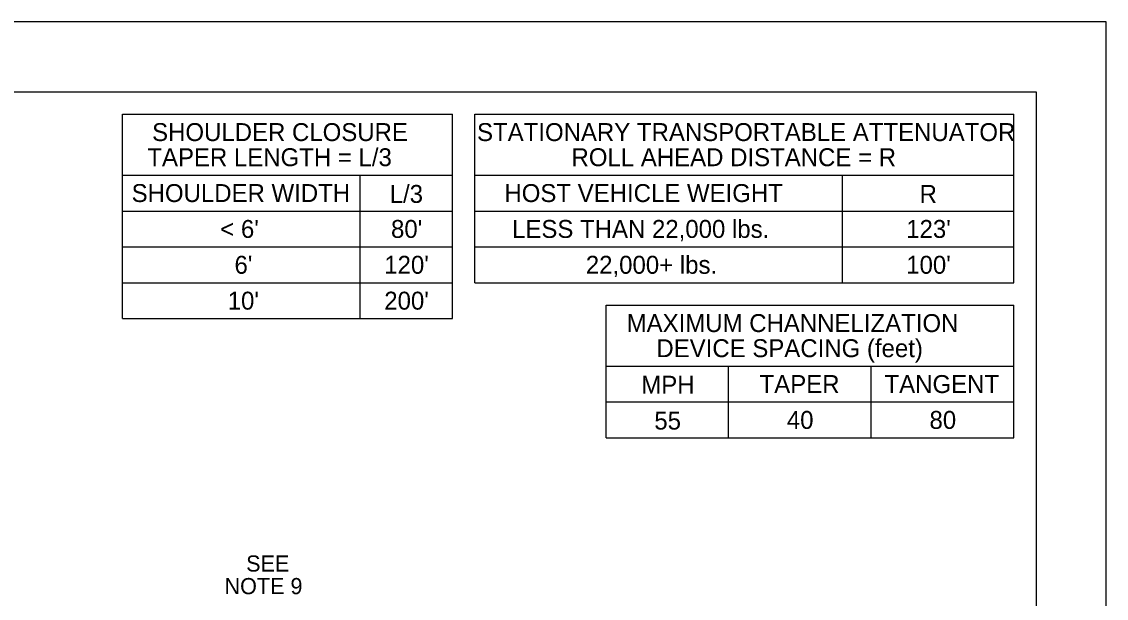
# Model space of a CAD drawing. Extents: x 99999 to 100116, y 99995 to 100013.
# Drawn here: x 100031.224 to 100036.062, y 100008.115 to 100010.687 of the extents above; entities that cross this region are included whole.
import ezdxf

# ---------------------------------------------------------------- set-up
doc = ezdxf.new("R2010")
doc.units = 0
for name, color, linetype in [('SH_GI_PlotLimits', 7, 'Continuous'), ('SH_GI_SheetBorder', 7, 'Continuous'), ('SH_TI_Tables', 7, 'Continuous'), ('TR_SN_ConstructionSigns', 7, 'Continuous')]:
    doc.layers.add(name, color=color, linetype=linetype)

msp = doc.modelspace()

# ---------------------------------------------------------------- linework, layer by layer
at = {"layer": 'SH_GI_PlotLimits'}
msp.add_lwpolyline([(100019.0625, 99999.6875), (100036.0625, 99999.6875), (100036.0625, 100010.6875), (100019.0625, 100010.6875)], close=True, dxfattribs=at)
at = {"layer": 'SH_GI_SheetBorder'}
for p, q in [((100020, 100010.375), (100035.75, 100010.375)), ((100035.75, 100010.375), (100035.75, 100000))]:
    msp.add_line(p, q, dxfattribs=at)
at = {"layer": 'SH_TI_Tables'}
for p, q in [((100031.6742, 100010.275), (100033.1454, 100010.275)), ((100031.6742, 100009.363), (100031.6742, 100010.275)), ((100033.1454, 100009.363), (100033.1454, 100010.275)), ((100033.2454, 100010.275), (100035.65, 100010.275)), ((100033.2454, 100009.523), (100033.2454, 100010.275)), ((100035.65, 100009.523), (100035.65, 100010.275)), ((100031.6742, 100010.003), (100033.1454, 100010.003)), ((100032.7319, 100010.003), (100032.7319, 100009.363)), ((100033.2454, 100010.003), (100034.8844, 100010.003)), ((100034.8844, 100010.003), (100034.8844, 100009.843)), ((100034.8844, 100010.003), (100035.65, 100010.003)), ((100031.6742, 100009.843), (100032.7319, 100009.843)), ((100032.7319, 100009.843), (100033.1454, 100009.843)), ((100033.2454, 100009.843), (100034.8844, 100009.843)), ((100034.8844, 100009.843), (100035.65, 100009.843)), ((100034.8844, 100009.843), (100034.8844, 100009.683)), ((100031.6742, 100009.683), (100032.7319, 100009.683)), ((100032.7319, 100009.683), (100033.1454, 100009.683)), ((100033.2454, 100009.683), (100034.8844, 100009.683)), ((100034.8844, 100009.683), (100035.65, 100009.683)), ((100034.8844, 100009.683), (100034.8844, 100009.523)), ((100031.6742, 100009.523), (100032.7319, 100009.523)), ((100032.7319, 100009.523), (100033.1454, 100009.523)), ((100033.2454, 100009.523), (100035.65, 100009.523)), ((100033.8318, 100009.423), (100035.65, 100009.423)), ((100033.8318, 100008.831), (100033.8318, 100009.423)), ((100035.65, 100008.831), (100035.65, 100009.423)), ((100031.6742, 100009.363), (100032.7319, 100009.363)), ((100032.7319, 100009.363), (100033.1454, 100009.363)), ((100033.8318, 100009.151), (100035.65, 100009.151)), ((100034.3773, 100008.831), (100034.3773, 100009.151)), ((100035.0136, 100008.831), (100035.0136, 100009.151)), ((100033.8318, 100008.991), (100034.3773, 100008.991)), ((100034.3773, 100008.991), (100035.0136, 100008.991)), ((100035.0136, 100008.991), (100035.65, 100008.991)), ((100033.8318, 100008.831), (100035.65, 100008.831))]:
    msp.add_line(p, q, dxfattribs=at)

# ---------------------------------------------------------------- texts
for s, p in [('SHOULDER CLOSURE', (100031.8055, 100010.155)), ('STATIONARY TRANSPORTABLE ATTENUATOR ', (100033.2552, 100010.155)), ('TAPER LENGTH = L/3', (100031.7842, 100010.043)), ('ROLL AHEAD DISTANCE = R', (100033.6767, 100010.043)), ('SHOULDER WIDTH', (100031.7142, 100009.883)), ('L/3', (100032.8654, 100009.8792)), ('HOST VEHICLE WEIGHT', (100033.3773, 100009.883)), ('R', (100035.2296, 100009.8792)), ("< 6'", (100032.1096, 100009.723)), ("80'", (100032.8714, 100009.723)), ('LESS THAN 22,000 lbs.', (100033.4114, 100009.723)), ("123'", (100035.1698, 100009.723)), ("6'", (100032.1731, 100009.563)), ("120'", (100032.8412, 100009.563)), ('22,000+ lbs.', (100033.7405, 100009.563)), ("100'", (100035.1698, 100009.563)), ("10'", (100032.1428, 100009.403)), ("200'", (100032.8412, 100009.403)), ('MAXIMUM CHANNELIZATION', (100033.9227, 100009.303)), ('DEVICE SPACING (feet)', (100034.0553, 100009.191)), ('MPH', (100033.9878, 100009.0279)), ('TAPER', (100034.5157, 100009.031)), ('TANGENT', (100035.0731, 100009.031)), ('40', (100034.6373, 100008.871)), ('80', (100035.2737, 100008.871))]:
    msp.add_text(s, height=0.08, rotation=360, dxfattribs=at).set_placement(p)
msp.add_text('55', height=0.08, dxfattribs=at).set_placement((100034.0461, 100008.8679))
at = {"layer": 'TR_SN_ConstructionSigns'}
for s, p in [('SEE', (100032.2251, 100008.2345)), ('NOTE 9', (100032.1286, 100008.1337))]:
    msp.add_text(s, height=0.072, rotation=360, dxfattribs=at).set_placement(p)

doc.saveas('drawing.dxf')
